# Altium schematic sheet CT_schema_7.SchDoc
size 252 x 159 mm
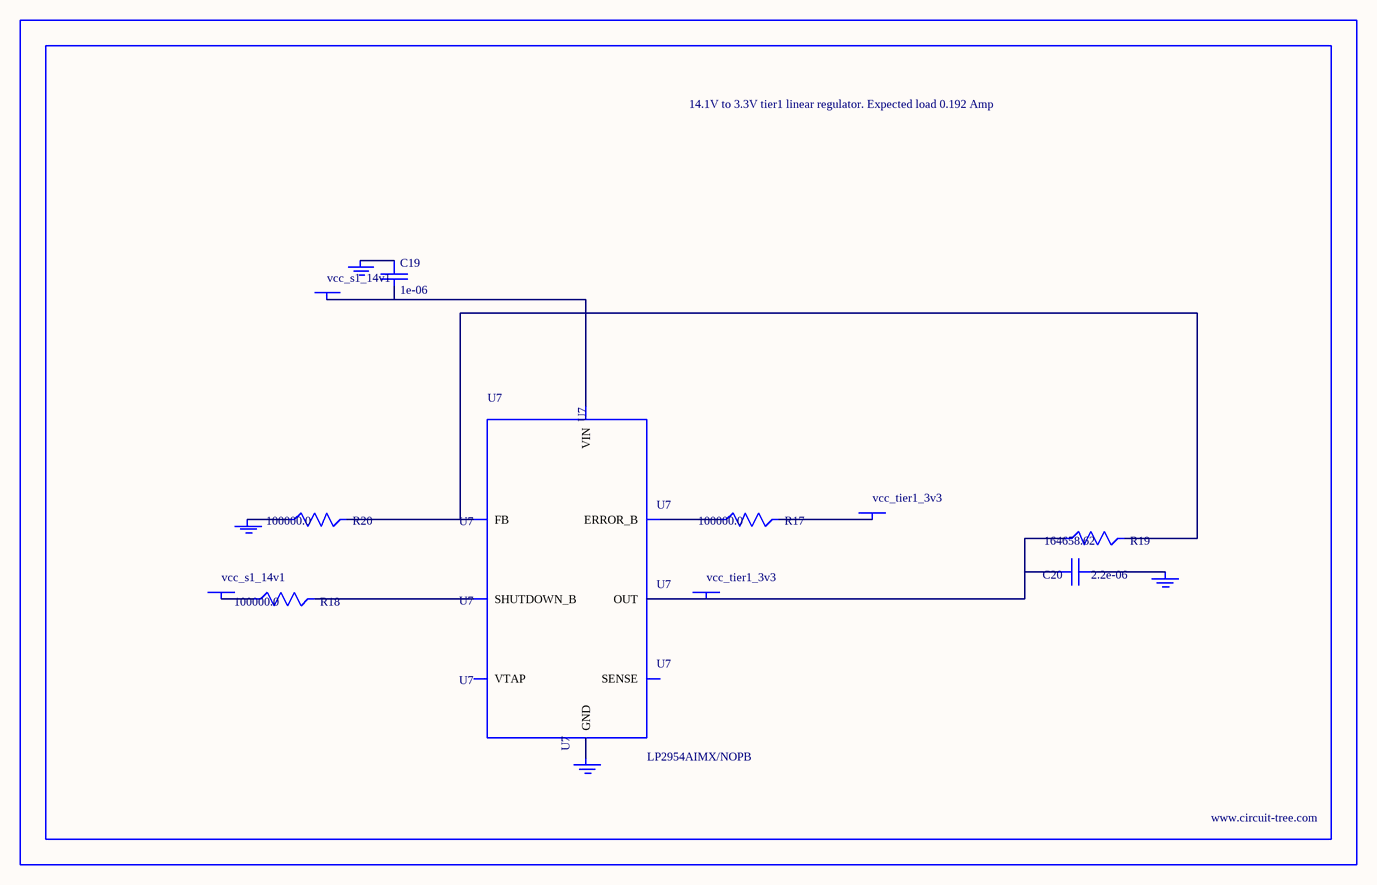
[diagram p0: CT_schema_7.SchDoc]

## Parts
BORDER6  (no value)
C19  1e-06  [EXV-9B]
C20  2.2e-06  [EXV-9B]
GND_INSTANCE_6_0  (no value)
GND_INSTANCE_6_1  (no value)
GND_INSTANCE_6_2  (no value)
GND_INSTANCE_6_3  (no value)
POWER_INSTANCE_6_0  vcc_s1_14v1
POWER_INSTANCE_6_1  vcc_tier1_3v3
POWER_INSTANCE_6_2  vcc_s1_14v1
POWER_INSTANCE_6_3  vcc_tier1_3v3
R17  100000.0  [R0603]
R18  100000.0  [R0603]
R19  164658.62  [R0603]
R20  100000.0  [R0603]
U7  LP2954AIMX/NOPB  [LP2954]

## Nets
NetC19_1: C19.1 GND_INSTANCE_6_2.0(GND)
NetC19_2: C19.2 POWER_INSTANCE_6_2.0(PWR) U7.8(VIN)
NetC20_1: C20.1 GND_INSTANCE_6_0.0(GND)
NetC20_2: C20.2 POWER_INSTANCE_6_3.0(PWR) R19.1 U7.1(OUT)
NetGND_INSTANCE_6_1_0: GND_INSTANCE_6_1.0(GND) R20.1
NetGND_INSTANCE_6_3_0: GND_INSTANCE_6_3.0(GND) U7.4(GND)
NetPOWER_INSTANCE_6_0_0: POWER_INSTANCE_6_0.0(PWR) R18.1
NetPOWER_INSTANCE_6_1_0: POWER_INSTANCE_6_1.0(PWR) R17.2
NetR17_1: R17.1 U7.5(ERROR_B)
NetR18_2: R18.2 U7.3(SHUTDOWN_B)
NetR19_2: R19.2 R20.2 U7.7(FB)

Not connected (* = marked no-connect by the designer): U7 2(SENSE) 6(VTAP)

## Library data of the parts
BORDER6 = BORDER_PAGE6
C19 = EDK105M050A9BAA
C20 = EDK225M050A9BAA
GND_INSTANCE_6_0-GND_INSTANCE_6_3 = GND
POWER_INSTANCE_6_0-POWER_INSTANCE_6_3 = PWR
R17 R18 R20 = RC0603JR-07100KL
R19 = R19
